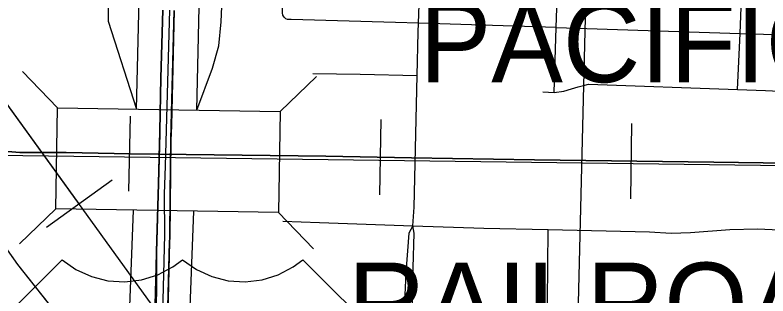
# Model space of a CAD drawing. Extents: x -132.8 to -73.3, y -60 to -26.
# Drawn here: x -125.444 to -124.694, y -50.132 to -49.852 of the extents above; entities that cross this region are included whole.
import ezdxf

# ---------------------------------------------------------------- set-up
doc = ezdxf.new("R2010")
doc.units = 0
for name, color, linetype in [('tdCoCityStreetMajor', 7, 'Continuous'), ('tdCoCityStreetMinor', 7, 'Continuous'), ('tdCoDivCarto', 7, 'Continuous'), ('tdCoInt', 7, 'Continuous'), ('tdCoIntCL', 7, 'Continuous'), ('tdCoIntRamp', 7, 'Continuous'), ('tdCoIntRte', 7, 'Continuous'), ('tdCoPipe', 7, 'Continuous'), ('tdCoPrimary', 7, 'Continuous'), ('tdCoRRCL', 7, 'Continuous'), ('tdCoRROwnerTxt', 7, 'Continuous'), ('tdCoSectLine', 7, 'Continuous'), ('tdCoShieldUsRte', 7, 'Continuous'), ('tdCoStrucNonDivPri', 7, 'Continuous')]:
    doc.layers.add(name, color=color, linetype=linetype)

msp = doc.modelspace()

# ---------------------------------------------------------------- linework, layer by layer
at = {"layer": 'tdCoCityStreetMajor'}
for points in [[(-125.04751, -50.06185), (-125.04642, -50.04344), (-125.04326, -49.91181), (-125.04223, -49.86885), (-125.04191, -49.85986), (-125.03963, -49.7955), (-125.03738, -49.73224)], [(-125.04751, -50.06185), (-125.0515, -50.06914), (-125.05454, -50.10869), (-125.05809, -50.18204)], [(-125.04914, -50.19609), (-125.04744, -50.10396), (-125.04626, -50.06931), (-125.04751, -50.06185)]]:
    msp.add_lwpolyline(points, dxfattribs=at)
at = {"layer": 'tdCoCityStreetMinor'}
for p, q in [((-124.90687, -49.92882), (-124.90477, -49.86421)), ((-124.90477, -49.86421), (-124.72156, -49.87003)), ((-124.724, -49.92608), (-124.72156, -49.87003)), ((-124.91814, -49.9284), (-124.90687, -49.92882))]:
    msp.add_line(p, q, dxfattribs=at)
for points in [[(-124.90477, -49.86421), (-125.04191, -49.85986), (-125.06509, -49.85913), (-125.16892, -49.85617), (-125.17262, -49.85601), (-125.17433, -49.85529), (-125.17598, -49.85386), (-125.17711, -49.85192), (-125.17765, -49.8495), (-125.17563, -49.7918)], [(-124.90477, -49.86421), (-124.90317, -49.81538), (-124.9028, -49.79921)], [(-124.72156, -49.87003), (-124.71966, -49.82627), (-124.7193, -49.81319)], [(-124.72156, -49.87003), (-124.70751, -49.87047), (-124.53347, -49.87665)], [(-125.14731, -49.90983), (-125.10003, -49.91073), (-125.04326, -49.91181)], [(-124.90687, -49.92882), (-124.89711, -49.92752), (-124.8894, -49.92542), (-124.88275, -49.92344), (-124.87626, -49.92156), (-124.87249, -49.92068), (-124.724, -49.92608)], [(-124.724, -49.92608), (-124.69616, -49.92709), (-124.64077, -49.9295)], [(-125.17729, -50.05737), (-125.14073, -50.05876), (-125.04751, -50.06185), (-124.97674, -50.06419), (-124.91275, -50.06562)], [(-124.91488, -50.20544), (-124.91384, -50.17335), (-124.91275, -50.06562)], [(-124.91275, -50.06562), (-124.81176, -50.06789), (-124.7903, -50.06912), (-124.77082, -50.06863), (-124.73161, -50.06567), (-124.70424, -50.06493), (-124.66749, -50.06665), (-124.64234, -50.06739)]]:
    msp.add_lwpolyline(points, dxfattribs=at)
at = {"layer": 'tdCoDivCarto'}
for p, q in [((-125.29675, -49.84672), (-125.29876, -49.91437)), ((-125.28797, -49.9619), (-125.28508, -49.84704)), ((-125.29876, -49.91437), (-125.29989, -49.96761)), ((-125.29989, -49.96761), (-125.29994, -49.96994)), ((-125.28817, -49.96975), (-125.28797, -49.9619)), ((-125.29994, -49.96994), (-125.30098, -50.01967)), ((-125.28833, -49.97602), (-125.28817, -49.96975)), ((-125.28956, -50.07393), (-125.28833, -49.97602)), ((-125.30098, -50.01967), (-125.30267, -50.0769)), ((-125.30267, -50.0769), (-125.303, -50.08796)), ((-125.30267, -50.0769), (-125.303, -50.08796)), ((-125.29039, -50.10626), (-125.28966, -50.07786)), ((-125.28966, -50.07786), (-125.28956, -50.07393)), ((-125.303, -50.08796), (-125.30344, -50.17765)), ((-125.29204, -50.17027), (-125.29039, -50.10626)), ((-125.29204, -50.17027), (-125.29039, -50.10626))]:
    msp.add_line(p, q, dxfattribs=at)
for points in [[(-125.29675, -49.84672), (-125.29876, -49.91437), (-125.29989, -49.96761), (-125.30098, -50.01967), (-125.303, -50.08796), (-125.30345, -50.10327), (-125.30539, -50.1786), (-125.30613, -50.20739)], [(-125.29675, -49.84672), (-125.29876, -49.91437), (-125.29989, -49.96761), (-125.30098, -50.01967), (-125.303, -50.08796), (-125.30345, -50.10327), (-125.30539, -50.1786), (-125.30613, -50.20739)], [(-125.29675, -49.84672), (-125.29876, -49.91437), (-125.29989, -49.96761), (-125.29994, -49.96994)], [(-125.28866, -50.00233), (-125.28833, -49.97602), (-125.28797, -49.9619), (-125.28508, -49.84704)], [(-125.28866, -50.00233), (-125.28833, -49.97602), (-125.28797, -49.9619), (-125.28508, -49.84704)], [(-125.28817, -49.96975), (-125.28797, -49.9619), (-125.28508, -49.84704)], [(-125.29994, -49.96994), (-125.30098, -50.01967), (-125.30267, -50.0769)], [(-125.29039, -50.10626), (-125.28966, -50.07786), (-125.28956, -50.07393), (-125.28833, -49.97602), (-125.28817, -49.96975)], [(-125.28901, -50.03018), (-125.28866, -50.00233)], [(-125.28901, -50.03018), (-125.28866, -50.00233)], [(-125.29301, -50.20773), (-125.28966, -50.07786), (-125.28956, -50.07393), (-125.28901, -50.03018)], [(-125.29204, -50.17027), (-125.28966, -50.07786), (-125.28956, -50.07393), (-125.28901, -50.03018)], [(-125.303, -50.08796), (-125.30344, -50.17765)]]:
    msp.add_lwpolyline(points, dxfattribs=at)
at = {"layer": 'tdCoInt'}
for points in [[(-125.32287, -49.94544), (-125.31786, -49.72638)], [(-125.26288, -49.94647), (-125.25783, -49.72589)], [(-125.01823, -50.82321), (-125.22187, -50.55129), (-125.25292, -50.50535), (-125.28043, -50.45117), (-125.30204, -50.3951), (-125.31549, -50.3425), (-125.32589, -50.28068), (-125.32935, -50.2264), (-125.32991, -50.1509), (-125.32587, -50.04615)], [(-124.92748, -50.84055), (-125.17247, -50.51715), (-125.2012, -50.47468), (-125.22555, -50.42673), (-125.24479, -50.37682), (-125.25673, -50.33007), (-125.26621, -50.27377), (-125.26937, -50.22427), (-125.26991, -50.15184), (-125.26587, -50.04717)]]:
    msp.add_lwpolyline(points, dxfattribs=at)
at = {"layer": 'tdCoIntCL'}
msp.add_lwpolyline([(-125.29853, -50.20759), (-125.29721, -50.16223), (-125.29471, -50.07091), (-125.29523, -50.03011), (-125.29416, -50.00226), (-125.29376, -49.99015), (-125.28975, -49.84694)], dxfattribs=at)
at = {"layer": 'tdCoIntRamp'}
for points in [[(-125.26288, -49.94647), (-125.24724, -49.9047), (-125.24095, -49.88226), (-125.2385, -49.85858), (-125.23686, -49.82027), (-125.23218, -49.79092), (-125.22971, -49.77218), (-125.22823, -49.75985), (-125.22798, -49.74727), (-125.22842, -49.72706)], [(-125.36101, -49.74718), (-125.36193, -49.76542), (-125.36075, -49.78818), (-125.35887, -49.80398), (-125.35592, -49.81694), (-125.35262, -49.83557), (-125.3512, -49.84359), (-125.35128, -49.85765), (-125.32287, -49.94544)]]:
    msp.add_lwpolyline(points, dxfattribs=at)
at = {"layer": 'tdCoIntRte'}
for points in [[(-125.29713, -49.84672), (-125.29914, -49.91437), (-125.30027, -49.96761), (-125.30136, -50.01967), (-125.30338, -50.08796), (-125.30383, -50.10327), (-125.30577, -50.1786)], [(-125.29713, -49.84672), (-125.29914, -49.91437), (-125.30027, -49.96761), (-125.30136, -50.01967), (-125.30338, -50.08796), (-125.30383, -50.10327), (-125.30577, -50.1786)], [(-125.29339, -50.20773), (-125.29004, -50.07786), (-125.28994, -50.07393), (-125.28939, -50.03018), (-125.28904, -50.00233), (-125.2887, -49.97602), (-125.28835, -49.9619), (-125.28546, -49.84704)], [(-125.29339, -50.20773), (-125.29004, -50.07786), (-125.28994, -50.07393), (-125.28939, -50.03018), (-125.28904, -50.00233), (-125.2887, -49.97602), (-125.28835, -49.9619), (-125.28546, -49.84704)]]:
    msp.add_lwpolyline(points, dxfattribs=at)
at = {"layer": 'tdCoPipe'}
msp.add_line((-125.34744, -50.01648), (-125.41274, -50.0636), dxfattribs=at)
for points in [[(-120.61806, -56.76184), (-120.51445, -55.55397), (-120.47938, -54.46793), (-120.46129, -53.94778), (-120.48621, -53.68107), (-120.63143, -53.41199), (-120.92646, -53.11014), (-121.6016, -52.44716), (-122.18422, -51.8754), (-122.8311, -51.72155), (-122.92518, -51.60843), (-123.07575, -51.61539), (-123.31203, -51.59481), (-123.55845, -51.16678), (-124.03386, -51.16929), (-124.73918, -50.72024), (-125.02763, -50.49401), (-125.29, -50.16499), (-125.83101, -49.41527)], [(-121.21573, -52.82232), (-121.68772, -52.7514), (-122.34953, -52.53964), (-122.86529, -52.34666), (-123.37271, -52.03464), (-123.83895, -51.66782), (-124.34957, -51.21071), (-124.84078, -50.78776), (-125.10644, -50.52423), (-125.44118, -50.10041), (-125.63639, -49.82438), (-125.73894, -49.63164), (-125.77869, -49.50967)], [(-125.38014, -50.04008), (-125.55647, -49.79572)], [(-125.33543, -50.2343), (-125.44118, -50.10041), (-125.51666, -49.99368)]]:
    msp.add_lwpolyline(points, dxfattribs=at)
at = {"layer": 'tdCoPrimary'}
for p, q in [((-125.30267, -50.0769), (-125.303, -50.08796)), ((-125.30267, -50.0769), (-125.303, -50.08796)), ((-125.29204, -50.17027), (-125.29039, -50.10626)), ((-125.29204, -50.17027), (-125.29039, -50.10626))]:
    msp.add_line(p, q, dxfattribs=at)
for points in [[(-125.29675, -49.84672), (-125.29876, -49.91437), (-125.29989, -49.96761), (-125.29994, -49.96994), (-125.30098, -50.01967), (-125.30267, -50.0769), (-125.303, -50.08796), (-125.30344, -50.17765)], [(-125.29675, -49.84672), (-125.29876, -49.91437), (-125.29989, -49.96761), (-125.29994, -49.96994)], [(-125.29675, -49.84672), (-125.29876, -49.91437), (-125.29989, -49.96761), (-125.29994, -49.96994)], [(-125.089, -50.66065), (-125.12869, -50.59113), (-125.19426, -50.47943), (-125.21307, -50.44674), (-125.22841, -50.41917), (-125.24095, -50.3967), (-125.25184, -50.37623), (-125.26157, -50.35495), (-125.26943, -50.33523), (-125.27722, -50.31202), (-125.28166, -50.29427), (-125.28634, -50.26887), (-125.28938, -50.24729), (-125.29177, -50.2263), (-125.29204, -50.17027), (-125.29039, -50.10626), (-125.28966, -50.07786), (-125.28956, -50.07393), (-125.28833, -49.97602), (-125.28817, -49.96975), (-125.28797, -49.9619), (-125.28508, -49.84704)], [(-125.28817, -49.96975), (-125.28797, -49.9619), (-125.28508, -49.84704)], [(-125.28817, -49.96975), (-125.28797, -49.9619), (-125.28508, -49.84704)], [(-125.29994, -49.96994), (-125.30098, -50.01967), (-125.30267, -50.0769)], [(-125.29994, -49.96994), (-125.30098, -50.01967), (-125.30267, -50.0769)], [(-125.29039, -50.10626), (-125.28966, -50.07786), (-125.28956, -50.07393), (-125.28833, -49.97602), (-125.28817, -49.96975)], [(-125.29039, -50.10626), (-125.28966, -50.07786), (-125.28956, -50.07393), (-125.28833, -49.97602), (-125.28817, -49.96975)], [(-125.303, -50.08796), (-125.30344, -50.17765)], [(-125.303, -50.08796), (-125.30344, -50.17765)]]:
    msp.add_lwpolyline(points, dxfattribs=at)
at = {"layer": 'tdCoRRCL'}
for p, q in [((-125.3306, -50.02743), (-125.32907, -49.95244)), ((-125.08052, -50.03102), (-125.0792, -49.95603)), ((-124.83033, -50.03487), (-124.82945, -49.95987)), ((-124.61232, -50.00305), (-125.93613, -49.98568))]:
    msp.add_line(p, q, dxfattribs=at)
for points in [[(-124.4516, -50.00305), (-124.47048, -50.00279), (-124.50114, -50.00219), (-124.55096, -50.00122), (-124.74782, -49.99833), (-124.92634, -49.99624), (-125.04883, -49.99408), (-125.04884, -49.99408), (-125.13422, -49.99257), (-125.16177, -49.9922), (-125.32925, -49.98995), (-125.39322, -49.98864), (-125.43935, -49.98864), (-125.45508, -49.98759), (-125.47579, -49.98575), (-125.48995, -49.98523), (-125.53507, -49.98401), (-125.5484, -49.98365), (-125.6973, -49.98182), (-125.76969, -49.98084), (-125.81395, -49.98025), (-125.82965, -49.98035)], [(-125.82965, -49.98035), (-125.81395, -49.98025), (-125.76969, -49.98084), (-125.6973, -49.98182), (-125.5484, -49.98365), (-125.53507, -49.98401), (-125.48995, -49.98523), (-125.47579, -49.98575), (-125.45508, -49.98759), (-125.43935, -49.98864), (-125.39322, -49.98864), (-125.32925, -49.98995), (-125.16177, -49.9922), (-125.13422, -49.99257), (-125.04884, -49.99408), (-125.04883, -49.99408), (-124.92634, -49.99624), (-124.74782, -49.99833), (-124.55096, -50.00122), (-124.50114, -50.00219), (-124.47048, -50.00279), (-124.4516, -50.00305)]]:
    msp.add_lwpolyline(points, dxfattribs=at)
at = {"layer": 'tdCoSectLine'}
msp.add_lwpolyline([(-124.8843, -50.20694), (-124.85997, -49.21679)], dxfattribs=at)
at = {"layer": 'tdCoShieldUsRte'}
msp.add_lwpolyline([(-125.47602, -50.17458), (-125.39715, -50.09571), (-125.38334, -50.10544), (-125.36798, -50.1125), (-125.3516, -50.11665), (-125.33474, -50.11776), (-125.31796, -50.11578), (-125.30181, -50.11078), (-125.28685, -50.10293), (-125.27714, -50.09571), (-125.26332, -50.10544), (-125.24797, -50.1125), (-125.23159, -50.11665), (-125.21473, -50.11776), (-125.19794, -50.11578), (-125.1818, -50.11078), (-125.16683, -50.10293), (-125.15712, -50.09571), (-125.07826, -50.17458)], dxfattribs=at)
at = {"layer": 'tdCoStrucNonDivPri'}
for p, q in [((-125.40163, -49.9441), (-125.43664, -49.90785)), ((-125.17995, -49.94788), (-125.1437, -49.91285)), ((-125.40335, -50.04483), (-125.40163, -49.9441)), ((-125.40163, -49.9441), (-125.17995, -49.94788)), ((-125.17995, -49.94788), (-125.18167, -50.04861)), ((-125.40335, -50.04483), (-125.43957, -50.07986)), ((-125.18167, -50.04861), (-125.40335, -50.04483)), ((-125.40335, -50.04483), (-125.40335, -50.04483)), ((-125.18167, -50.04861), (-125.14664, -50.08486))]:
    msp.add_line(p, q, dxfattribs=at)

# ---------------------------------------------------------------- texts
at = {"layer": 'tdCoRROwnerTxt'}
for s, p in [('PACIFIC', (-125.04087, -49.91865)), ('RAILROAD', (-125.11227, -50.17865))]:
    msp.add_text(s, height=0.08, dxfattribs=at).set_placement(p)

doc.saveas('drawing.dxf')
